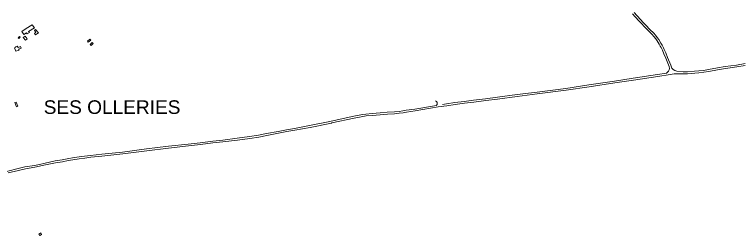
# Model space of a CAD drawing. Extents: x 476989 to 498418, y 4381813 to 4416555.
# Drawn here: x 485528 to 487660, y 4384718 to 4385368 of the extents above; entities that cross this region are included whole.
import ezdxf
from ezdxf.enums import TextEntityAlignment as Align

# ---------------------------------------------------------------- set-up
doc = ezdxf.new("R2010")
doc.units = 0
doc.header["$LTSCALE"] = 20
doc.linetypes.add('MEDIUM_DASHED', pattern=[4.5, 3, -1.5])
for name, color, linetype, lineweight in [('36', 7, 'Continuous', 13), ('47', 7, 'Continuous', 13), ('48', 7, 'MEDIUM_DASHED', 13)]:
    doc.layers.add(name, color=color, linetype=linetype, lineweight=lineweight)
doc.layers.add('7', color=7, linetype='Continuous')

msp = doc.modelspace()

# ---------------------------------------------------------------- linework, layer by layer
at = {"layer": '36'}
for points in [[(487348.1, 4385370.63), (487356.37, 4385361.74), (487367.97, 4385348.97), (487374.33, 4385342.13), (487383.49, 4385332.54), (487395.25, 4385320.59), (487406.19, 4385309.18), (487411.15, 4385303.84), (487416.54, 4385297.24), (487421.12, 4385291.23), (487426.69, 4385281.31), (487429.91, 4385275.71), (487432.17, 4385271.1), (487434.44, 4385267.53), (487436.19, 4385263.29), (487440.62, 4385253.02), (487445.84, 4385239.74), (487455.81, 4385215.58)], [(487352.58, 4385374.47), (487360.7, 4385365.72), (487372.3, 4385352.95), (487378.61, 4385346.17), (487387.71, 4385336.64), (487399.47, 4385324.69), (487410.47, 4385313.22), (487415.59, 4385307.71), (487421.16, 4385300.88), (487426.05, 4385294.47), (487431.8, 4385284.22), (487435.11, 4385278.47), (487437.31, 4385273.99), (487439.69, 4385270.26), (487441.61, 4385265.57), (487446.06, 4385255.26), (487451.29, 4385241.96), (487461.05, 4385218.86)], [(485509.45, 4384902.29), (485539.74, 4384909.58), (485559.9, 4384914.32), (485587.94, 4384918.87), (485619.65, 4384925.47), (485648.99, 4384932.03), (485669.04, 4384935.03), (485686.15, 4384938.36), (485699.65, 4384940.84), (485718.69, 4384943.79), (485734.94, 4384945.58), (485752.53, 4384948.26), (485785.29, 4384951.54), (485846.98, 4384958.08), (485917.59, 4384967.28), (485981.92, 4384974.91), (486040.54, 4384981.65), (486075.35, 4384985.5), (486112.55, 4384990.45), (486141.85, 4384993.18), (486184.72, 4384998.94), (486220.81, 4385003.83), (486247.67, 4385007.48), (486271.61, 4385012.25), (486305.54, 4385018.75), (486329.76, 4385023.58), (486353.89, 4385027.57), (486398.31, 4385035.88), (486461.13, 4385048.69), (486462.73, 4385049.14), (486528.81, 4385063.65), (486553.7, 4385068.46), (486563.83, 4385069.82), (486581.63, 4385071.52), (486605.36, 4385073.58), (486626.31, 4385074.93), (486647.28, 4385076.51), (486661.18, 4385077.81), (486672.55, 4385078.92), (486682.57, 4385080.87), (486708.05, 4385084.63), (486775.37, 4385096.2), (486800.8, 4385100.04), (486825.52, 4385103.44), (486853.12, 4385107.17), (486880.63, 4385110.38), (486915.74, 4385115.13), (486950.76, 4385119.43), (487008.87, 4385126.93), (487067.66, 4385134.49), (487152.91, 4385145.5), (487220.82, 4385155.63), (487295.65, 4385167.08), (487350.85, 4385175.59), (487422.95, 4385186.43), (487459.43, 4385191.37), (487470.68, 4385193.32), (487489.65, 4385193.71), (487510.01, 4385193.94), (487531.2, 4385196.06), (487543.67, 4385196.93), (487557.74, 4385198.3), (487572.8, 4385201.01), (487598.91, 4385205.81), (487622.06, 4385209.39), (487655.21, 4385214.16), (487679.8, 4385218.38)], [(487455.81, 4385215.58), (487456.62, 4385209.72), (487455.81, 4385205.68), (487454.49, 4385202.09), (487452.5, 4385199.34), (487448.32, 4385195.53)], [(487461.05, 4385218.86), (487463.98, 4385210.29), (487467.68, 4385206.41), (487472.37, 4385203.71), (487478.72, 4385201.9), (487497.15, 4385199.42)], [(487497.15, 4385199.42), (487509.69, 4385199.56), (487530.73, 4385201.64), (487543.2, 4385202.51), (487556.97, 4385203.85), (487571.79, 4385206.52), (487597.97, 4385211.35), (487621.23, 4385214.93), (487654.34, 4385219.7), (487679.81, 4385224.07)], [(486788.13, 4385103.8), (486799.99, 4385105.59), (486824.76, 4385108.99), (486852.42, 4385112.73), (486879.93, 4385115.94), (486915.02, 4385120.69), (486950.06, 4385124.99), (487008.15, 4385132.49), (487066.94, 4385140.05), (487152.14, 4385151.05), (487219.98, 4385161.17), (487294.79, 4385172.63), (487350, 4385181.14), (487422.16, 4385191.98), (487448.32, 4385195.53)], [(485601.44, 4384927.38), (485618.46, 4384930.95), (485647.97, 4384937.54), (485668, 4384940.55), (485688.12, 4384944.59), (485698.86, 4384946.38), (485717.96, 4384949.34), (485734.21, 4384951.14), (485751.82, 4384953.82), (485784.71, 4384957.11), (485846.33, 4384963.64), (485916.89, 4384972.84), (485981.27, 4384980.47), (486039.91, 4384987.22), (486074.67, 4384991.06), (486111.92, 4384996.02), (486141.22, 4384998.75), (486183.97, 4385004.49), (486220.05, 4385009.38), (486246.73, 4385013.02), (486270.53, 4385017.75), (486304.46, 4385024.25), (486328.75, 4385029.09), (486352.92, 4385033.1), (486397.22, 4385041.38), (486452.17, 4385052.61), (486452.19, 4385052.58), (486527.68, 4385069.14), (486552.8, 4385074), (486563.2, 4385075.39), (486581.12, 4385077.1), (486604.95, 4385079.16), (486625.92, 4385080.52), (486646.81, 4385082.09), (486660.65, 4385083.38), (486671.74, 4385084.47), (486681.62, 4385086.4), (486707.17, 4385090.17), (486770.61, 4385101.07)], [(485422.69, 4384896.4), (485445.04, 4384898.28), (485457.06, 4384899.22), (485464.89, 4384900.34), (485474.69, 4384902.21), (485508.34, 4384907.79), (485538.44, 4384915.04), (485558.81, 4384919.82), (485586.93, 4384924.38), (485601.44, 4384927.38)]]:
    msp.add_lwpolyline(points, dxfattribs=at)
msp.add_spline([(486767.68, 4385114.39), (486772.5, 4385109.36), (486772.99, 4385106.58), (486772.97, 4385105.38), (486772.81, 4385104.41), (486772.42, 4385103.66), (486770.74, 4385101.28), (486770.61, 4385101.07)], degree=3, dxfattribs=at)
at = {"layer": '47'}
for points in [[(485549.71, 4385318.83), (485561.98, 4385326.75), (485580.37, 4385337.6), (485587.23, 4385328.94), (485569.52, 4385318.84), (485571.72, 4385315.06), (485565.44, 4385311.55), (485563.46, 4385314.43), (485555.65, 4385309.29)], [(485590.08, 4385308.34), (485598.5, 4385314.38), (485590.16, 4385324.25), (485586.82, 4385321.45), (485590.88, 4385316.59), (485586.69, 4385312.74)], [(485542.75, 4385303.99), (485538.6, 4385300.17), (485540.85, 4385297.49), (485545.11, 4385301.63)], [(485559.04, 4385304.89), (485565.52, 4385297.05), (485560.45, 4385292.86), (485553.97, 4385300.7)], [(485750.18, 4385295.54), (485742.99, 4385289.76), (485745.4, 4385286.76), (485752.59, 4385292.54)], [(485535.88, 4385275.28), (485538.53, 4385271.26), (485545.24, 4385273.79), (485547.35, 4385269.41), (485540.18, 4385266.44), (485542.09, 4385263.63), (485532.37, 4385260.7), (485528.09, 4385270.51), (485532.09, 4385272.56), (485531.74, 4385273.91)], [(485756.95, 4385286.22), (485750.76, 4385280.13), (485753.96, 4385276.88), (485760.15, 4385282.97)], [(485532.7, 4385110.77), (485537.34, 4385098.3), (485534.08, 4385097.09), (485529.44, 4385109.56)]]:
    msp.add_lwpolyline(points, close=True, dxfattribs=at)
at = {"layer": '48'}
msp.add_lwpolyline([(485599.77, 4384722.32), (485605.45, 4384725.41), (485607.85, 4384721), (485602.17, 4384717.91)], close=True, dxfattribs=at)

# ---------------------------------------------------------------- texts
at = {"layer": '7', "width": 1.05}
msp.add_text('SES OLLERIES', height=40, dxfattribs=at).set_placement((485815.34, 4385075.83), align=Align.CENTER)

doc.saveas('drawing.dxf')
